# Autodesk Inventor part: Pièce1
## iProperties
Shininess: 64.0
Length Units: 11269
Angle Units: 11279
Time Units: 11290
Mass Units: 11283
Length Display Precision: 3
Angle Display Precision: 2
Compacted: True
Part Number: Pièce1
Document SubType Name: Modeling
Created: 2004-06
Material: Par défaut
Designer: administrateur
Density: 0.0
Volumn: 0.0
Area: 0.0
PropertySet Name: Model Information
Control State: 0
Master: False
Checked Out: False
Author: administrateur
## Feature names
1. Extrusion1
